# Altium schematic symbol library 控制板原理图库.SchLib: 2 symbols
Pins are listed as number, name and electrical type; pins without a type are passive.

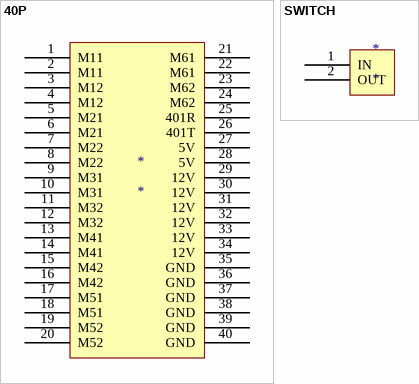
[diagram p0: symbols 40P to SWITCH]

## 40P
designator *
footprint PCBComponent_1
pins: 1 M11, 2 M11, 3 M12, 4 M12, 5 M21, 6 M21, 7 M22, 8 M22, 9 M31, 10 M31, 11 M32, 12 M32, 13 M41, 14 M41, 15 M42, 16 M42, 17 M51, 18 M51, 19 M52, 20 M52, 21 M61, 22 M61, 23 M62, 24 M62, 25 401R, 26 401T, 27 5V, 28 5V, 29 12V, 30 12V, 31 12V, 32 12V, 33 12V, 34 12V, 35 GND, 36 GND, 37 GND, 38 GND, 39 GND, 40 GND

## SWITCH
designator *
footprint switch
pins: 1 IN, 2 OUT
